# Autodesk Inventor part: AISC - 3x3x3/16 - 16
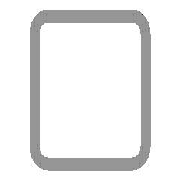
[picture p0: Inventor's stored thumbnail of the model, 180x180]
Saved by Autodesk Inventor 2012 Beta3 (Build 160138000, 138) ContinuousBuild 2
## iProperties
IsCustomPart: 1
_CCFamilyMember: 9
_CCFamilyDisplayName: ANSI AISC (Square) - Tube
_FrameMemberDoc: Frame Member File
_Version: 15.0.0
_GetPNFromCC: 1
Created: 2010-11
Part Number: AISC - 3x3x3/16 - 16
Material: Steel, Mild
Description: Tube
Document SubType Name: Modeling
Standard: ANSI
Designer: Beta-8540w
Standards Organization: ANSI
Language: en-US
Size Designation: 3x3x3/16
Categories: <MemberInstance><Categories><Category DisplayName="Structural Shapes" InternalName="089c4875-fa83-4c05-b084-43b9cc11f5ed" Mnemonic="GRDR"><CategoryParameter Dis
Stock Number: 3x3x3/16
Density: 7.86 g/cm^3
G_L: 16.000 in
G_W: 3.000 in
G_H: 3.000 in
Author: Beta-8540w
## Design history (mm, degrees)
node "Start plane"
node "End plane"
sketch "Sketch"
  geometry: L1 (-38.1, -28.575)-(-38.1, 28.575); L2 (-28.575, 38.1)-(28.575, 38.1); L3 (38.1, 28.575)-(38.1, -28.575); L4 (28.575, -38.1)-(-28.575, -38.1); L5 (-28.575, 33.337)-(28.575, 33.338); L6 (33.338, 28.575)-(33.338, -28.575); L7 (28.575, -33.337)-(-28.575, -33.338); L8 (-33.338, -28.575)-(-33.338, 28.575); L9 (0, 56.102)-(0, -56.102) reference; L10 (-56.102, 0)-(56.102, 0) reference; A1 r 9.525 centre (-28.575, -28.575) between (-38.1, -28.575) and (-28.575, -38.1); A2 r 9.525 centre (-28.575, 28.575) between (-28.575, 38.1) and (-38.1, 28.575); A3 r 9.525 centre (28.575, 28.575) between (38.1, 28.575) and (28.575, 38.1); A4 r 9.525 centre (28.575, -28.575) between (28.575, -38.1) and (38.1, -28.575); A5 r 4.763 centre (-28.575, 28.575) between (-28.575, 33.337) and (-33.338, 28.575); A6 r 4.763 centre (28.575, 28.575) between (33.338, 28.575) and (28.575, 33.338); A7 r 4.763 centre (28.575, -28.575) between (28.575, -33.337) and (33.338, -28.575); A8 r 4.763 centre (-28.575, -28.575) between (-33.338, -28.575) and (-28.575, -33.338)
  constraints: 16 end point, 16 point on circle, 8 centre point, 8 tangent, 4 parallel, 3 equal radius, 2 perpendicular, 7 other
  dimensions: "d10" = 76.2 distance between parallel lines of L2 L4 (= G_H); "d11" = 76.2 distance between parallel lines of L1 L3 (= G_W); "d12" = 4.7625 distance between parallel lines of L3 L6 (= G_T); "d15" = 38.1 distance between parallel lines of L2 L10 (= 0.5 x d10); "d16" = 38.1 distance between parallel lines of L9 L3 (= 0.5 x d11); "d17" = 9.525 radius of A1 (= G_IR)
extrude "Body" new body sketch "Sketch" stored distance "d3" = 406.4 (= G_L); taper "d4" = 0 deg
node "Driven Length"
  sketch "Sketch3"
    geometry: L1 (0, 0)-(10, 0) reference
    constraints: 2 end point, 1 horizontal
  workplane "Work Plane3"
  sketch "Sketch4"
    geometry: L1 (-2, -114.3)-(12, -114.3) reference; L2 (-2, 292.1)-(12, 292.1) reference
    dimensions: "d19" = 406.4 distance between parallel lines of L1 L2 (derived)
workplane "Work Plane4"
split "Split1"
body "Solid1"
other parameters: "G_W" = 76.2 [user parameter; used in 1 equation term], "G_H" = 76.2 [user parameter; used in 1 equation term], "G_T" = 4.7625 [user parameter; used in 1 equation term], "G_IR" = 9.525 [user parameter; used in 1 equation term], "G_L" = 406.4 (= d19) [user parameter; used in 1 equation term], "G_OFFSET_START" = 114.3 [user parameter; used in 1 equation term], "G_OFFSET_END" = 38.1 [user parameter; used in 1 equation term], "d13" = -114.3 (= -G_OFFSET_START), "d14" = 292.1 (= G_OFFSET_END + B_L), "B_L" = 254 [user parameter; used in 1 equation term], "d18" = 90 deg
